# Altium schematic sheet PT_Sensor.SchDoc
size A4
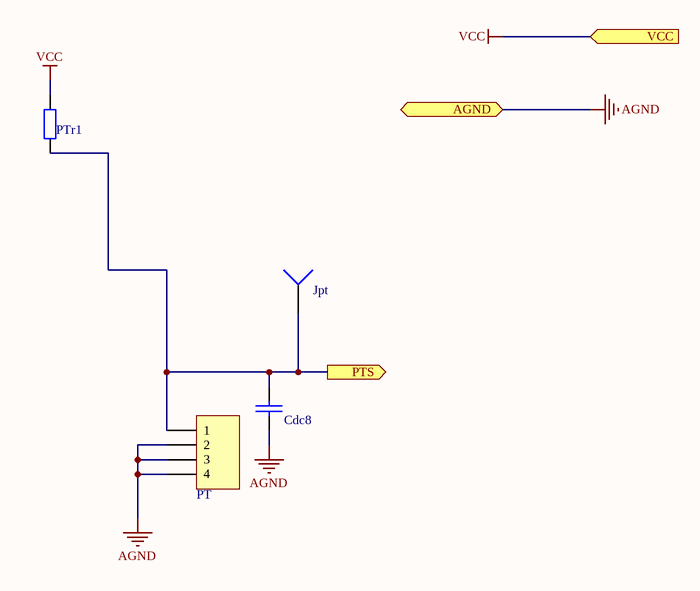
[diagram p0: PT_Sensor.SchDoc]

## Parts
Cdc8  47nF  [ECE-CAPC2012-0805SM]  (value not drawn)
Jpt  TEST PIN  [ECE-HDR1TH]  (value not drawn)
PT  4 Way  [ECE-600104STTH]  (value not drawn)
PTr1  39K  [ECE-RESC1608-0603SM]  (value not drawn)

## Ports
AGND (bidir), PTS (out), VCC (in)

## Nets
AGND: Cdc8.2 PT.2 PT.3 PT.4 ; port AGND
VCC: PTr1.2 ; port VCC
PTS: Cdc8.1 Jpt.1 PT.1 PTr1.1 ; port PTS

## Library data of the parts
Cdc8 = CAP000522: CAP CER 47nF 50V X7R SM0805; Manufactuer: Samsung; Manufacturer-PN: CL21B473KBCNNNC; Assembly Method: Surface Mount; Item Type: Item; Path: ece/ts/Lists/Stock Inventory
Jpt = CON000017: Value: 1 way; Assembly Method: Through hole; Item Type: Item; Path: ece/ts/Lists/Stock Inventory
PT = CON000003: HEADER POLARISED 4WAY TH; Manufactuer: GTK; Manufacturer-PN: 600104ST; Assembly Method: Through hole; Item Type: Item; Path: ece/ts/Lists/Stock Inventory
PTr1 = RES000157: RES CER 39K 1608 SM; Manufactuer: Yageo; Manufacturer-PN: RC0603FR-0739KL; Assembly Method: Surface Mount; Voltage/Current: 1/10W; Item Type: Item; Path: ece/ts/Lists/Stock Inventory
